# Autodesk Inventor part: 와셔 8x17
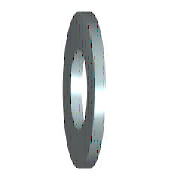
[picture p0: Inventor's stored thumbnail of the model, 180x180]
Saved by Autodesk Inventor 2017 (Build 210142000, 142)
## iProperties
Created: 2012-02
Part Number: 와셔 8x17
Material: 강철, 연강
Description: 평면 와셔
Document SubType Name: Modeling
Standard: KS B 1326
Designer: mduedu
Standards Organization: KS
Language: ko-KR
Size Designation: 8x17
Categories: <MemberInstance><Categories><Category DisplayName="조임쇠" InternalName="e4da775c-781d-43d5-af7c-5136215cf5a6" Mnemonic="FSTN"><Category DisplayName="와셔" InternalN
Density: 7.85 g/cm^3
Mass: 2.05184 g
Surface Area: 4.57416 cm^2
Volume: 0.261381 cm^3
Appearance: 파란색 - 벽 페인트 - 광택
IsCustomPart: 1
Author: mduedu
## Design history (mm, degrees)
sketch "스케치"
  geometry: C1 r 8.5 at (0, 0); C2 r 4.5 at (0, 0); 1 further point
  constraints: 2 centre point, 2 coincident
  dimensions: "d0" = 9 diameter of C2 (= SD1); "d1" = 17 diameter of C1 (= SD2)
extrude "본체" new body sketch "스케치" distance "d2" = 1.6 (= SD); taper "d3" = 0 deg
workaxis "Work Axis1"
workplane "Work Plane1"
body "Solid1"
other parameters: "SD1" = 9 [user parameter; used in 1 equation term], "SD2" = 17 [user parameter; used in 1 equation term], "SD" = 1.6 [user parameter; used in 1 equation term], "d4" = 0, "d5" = 0, "d6" = 0, "d7" = 0, "NND" = 8 [user parameter]
